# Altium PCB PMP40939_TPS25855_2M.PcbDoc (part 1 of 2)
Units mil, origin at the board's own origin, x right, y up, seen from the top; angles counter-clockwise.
Board outline 1968.5 x 1377.95 mil, 4 copper layers (Top Layer, Signal Layer 1, Signal Layer 2, Bottom Layer), stack 64.835 mil thick; 75 components, 24 nets, 187 pads, 267 vias.
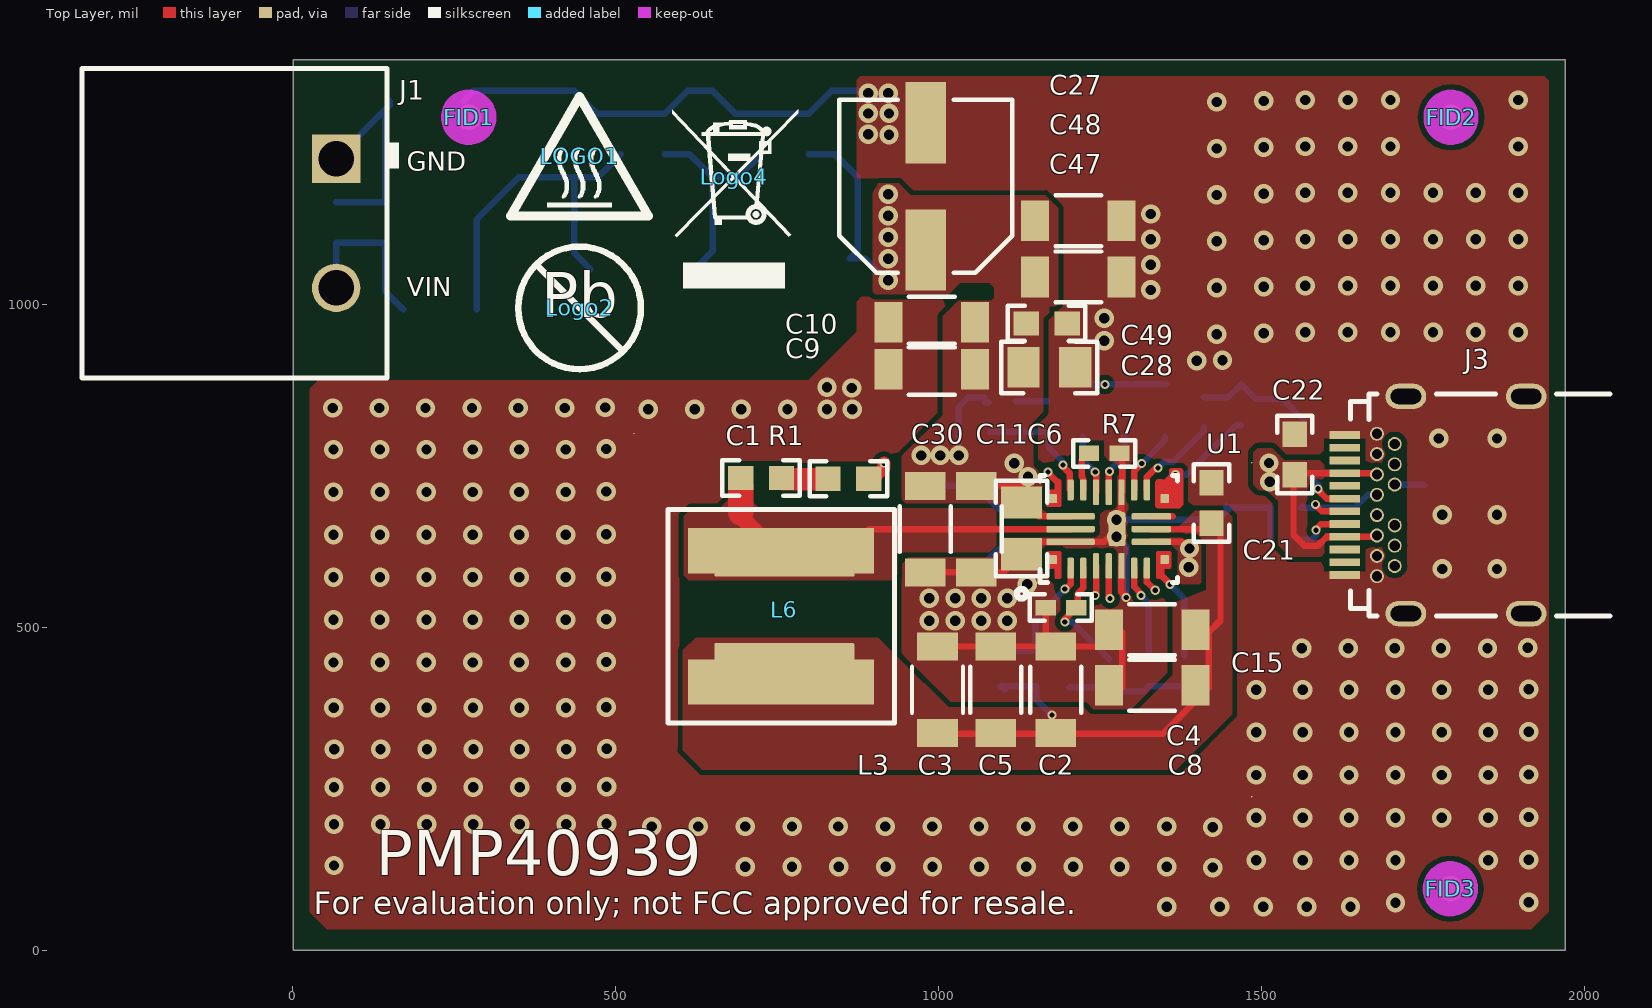
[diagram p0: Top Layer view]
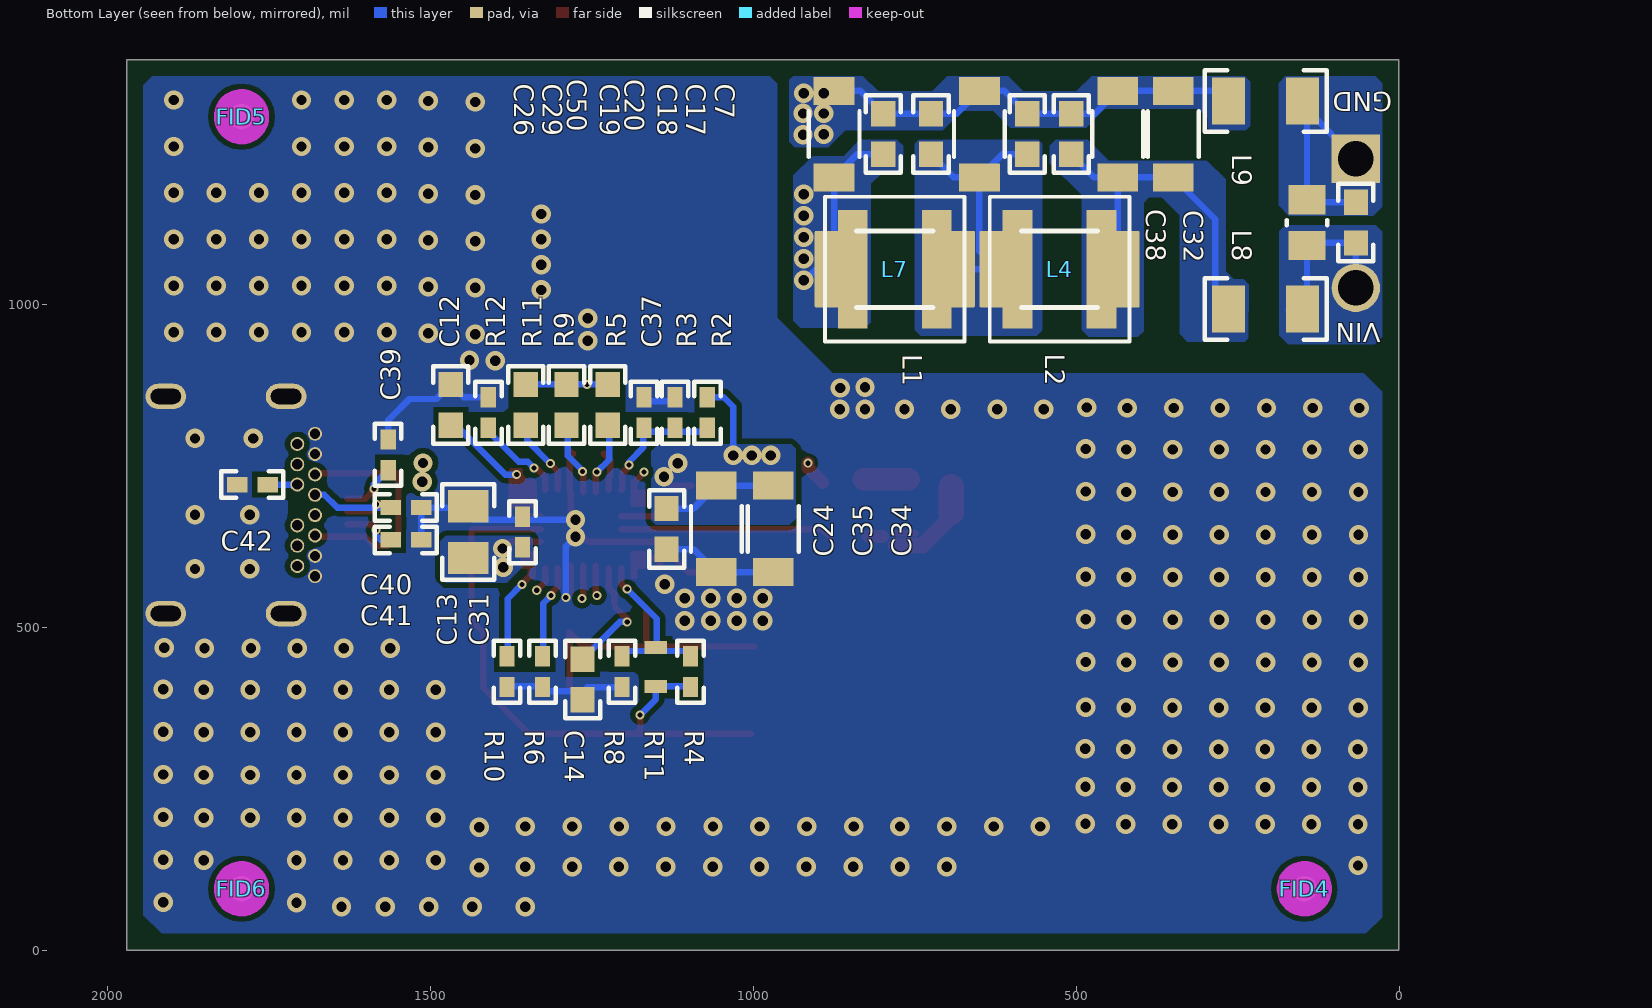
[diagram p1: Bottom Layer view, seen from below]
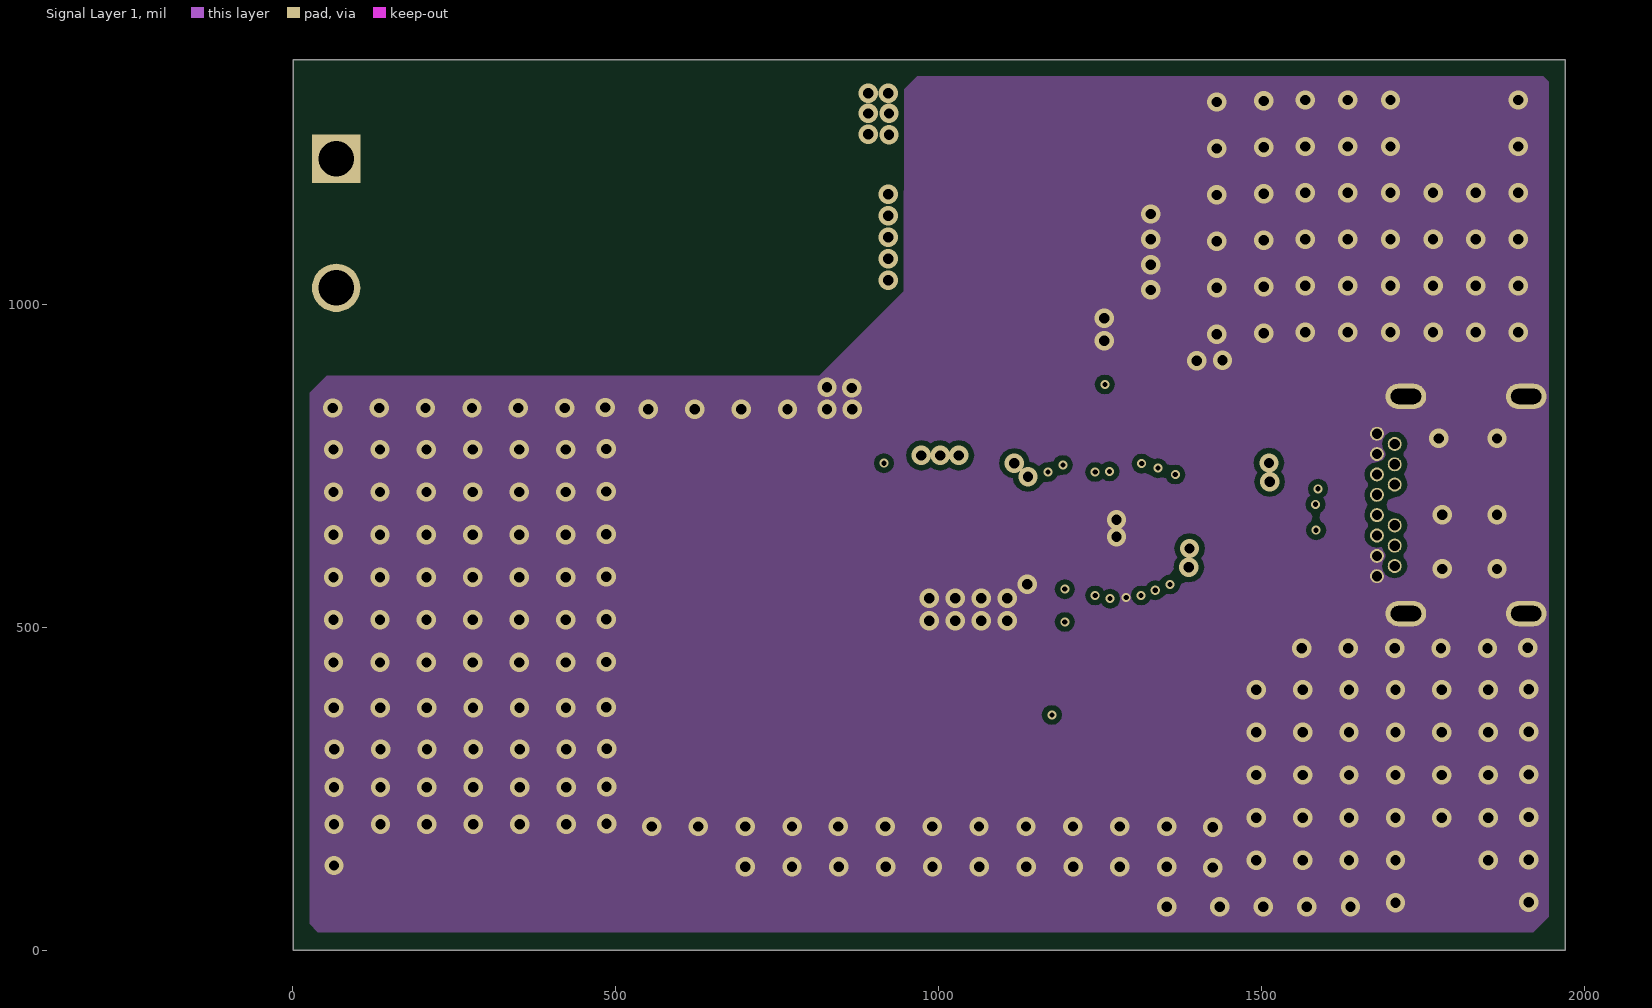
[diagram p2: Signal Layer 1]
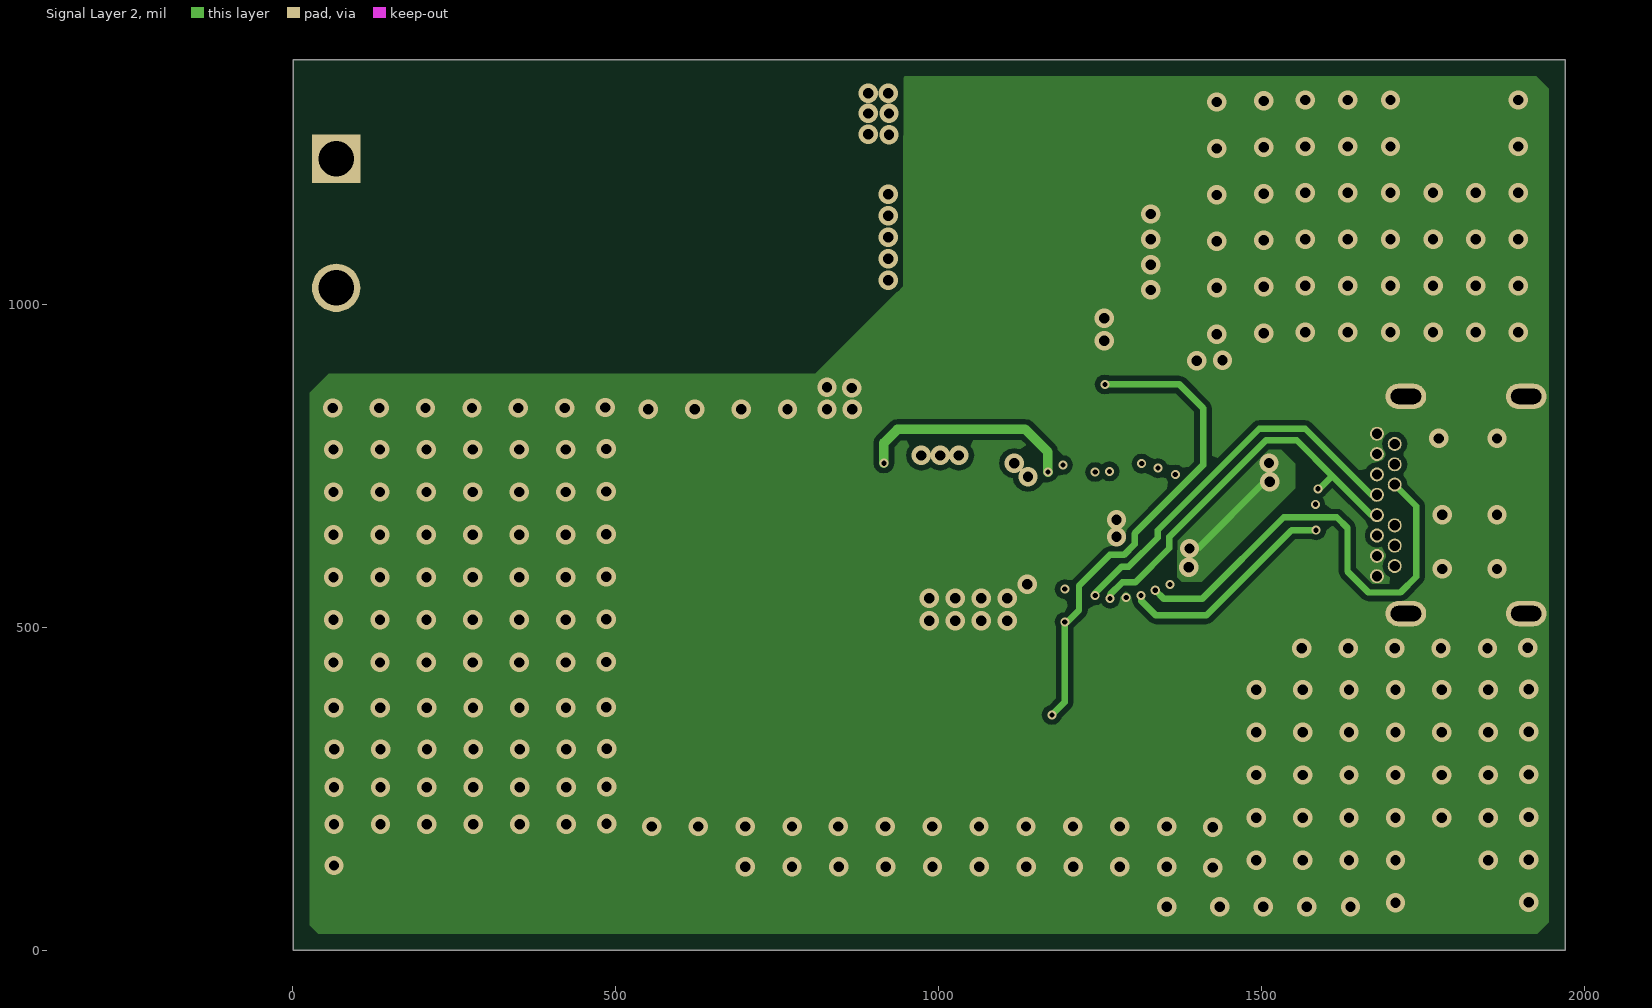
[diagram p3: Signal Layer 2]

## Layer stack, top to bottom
Top Solder: solder mask 0.4, Solder Resist, Dk 3.5
Top Layer: signal copper 1.4
Signal Layer 1: signal copper 1.4173
Signal Layer 2: signal copper 1.4173
Dielectric1: core 59.2, FR-4, Dk 4.8
Bottom Layer: signal copper 1.4
Bottom Solder: solder mask 0.4, Solder Resist, Dk 3.5

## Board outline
0.81,0.01 0.81,1377.96 1969.31,1377.96 1969.31,0.01

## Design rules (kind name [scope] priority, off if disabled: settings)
AcuteAngle [All] p1: minimum=4.50000000000000E+0001 checktracksonly=FALSE
AssemblyTestPointUsage [All] p1: valid=2
BoardOutlineClearance BoardOutlineClearance_MountingHoles [OnCopper and InComponentClass('Mounting Holes')] p1: gap=25 ignorepadtopadclearanceinfootprint=FALSE
BoardOutlineClearance BoardOutlineClearance_Poly [OnCopper and IsPoly] p2: gap=25 ignorepadtopadclearanceinfootprint=FALSE
BoardOutlineClearance [OnCopper and Not InComponentClass('Logo') and not InComponentClass('FiducialMark') and not InRegion(1000,500,4000,800) and not InPoly] p3: gap=24 ignorepadtopadclearanceinfootprint=FALSE
Clearance Clearance_1 [All] p1: gap=8 ignorepadtopadclearanceinfootprint=FALSE
Clearance Clearance_Keepouts [((IsTrack Or IsArc) And Not InPoly) And IsFree and IsKeepOut vs ((IsTrack Or IsArc) And Not InPoly) And IsFree and IsKeepOut] p2: gap=0 ignorepadtopadclearanceinfootprint=FALSE
Clearance Clearance_Poly [InPolygon] p3: gap=10 ignorepadtopadclearanceinfootprint=TRUE
Clearance Clearance_FiducialMark [IsKeepOut and InComponentClass('FiducialMark') vs IsPad and InComponentClass('FiducialMark')] p4: gap=0 ignorepadtopadclearanceinfootprint=FALSE
Clearance [All] p5: gap=6 ignorepadtopadclearanceinfootprint=TRUE
ComponentClearance ComponentClearance_MountingHoles_FiducialMarks [InComponentClass('Mounting Holes') vs InComponentClass('FiducialMark')] p1: gap=50 collisioncheckmode=3 verticalgap=10 showdistances=FALSE
ComponentClearance ComponentClearance_Shunt [InComponentClass('Header') vs InComponentClass('Shunt')] p2: gap=0 collisioncheckmode=3 verticalgap=0 showdistances=FALSE
ComponentClearance ComponentClearance_Logo [InComponentClass('Logo')] p3: gap=50 collisioncheckmode=3 verticalgap=10 showdistances=FALSE
ComponentClearance ComponentClearance_ScrewToNut [(HasFootprint('NY PMS 440 0025 PH')) vs (HasFootprint('Keystone_1902C'))] p4: gap=5 collisioncheckmode=3 verticalgap=10 showdistances=FALSE
ComponentClearance ComponentClearance_MountingHoles [InComponentClass('Mounting Holes')] p5: gap=250 collisioncheckmode=3 verticalgap=100000 showdistances=FALSE
ComponentClearance ComponentClearance_SmallPassives [HasFootprint('0201*') or HasFootprint('0402*') or HasFootprint('0508') or HasFootprint('0603*') or HasFootprint('0612') or HasFootprint('0805*') or HasFootprint('0815*') or HasFootprint('0830*') or HasFootprint('1206*') or HasFootprint('1210*') or HasFootprint('1808*') or HasFootprint('1812*') or HasFootprint('1825*') or HasFootprint('2010*') or HasFootprint('2220*') or HasFootprint('2225*') or HasFootprint('2512*') or HasFootprint('2728*') or HasFootprint('3518*') vs HasFootprint('0201*') or HasFootprint('0402*') or HasFootprint('0508') or HasFootprint('0603*') or HasFootprint('0612') or HasFootprint('0805*') or HasFootprint('0815*') or HasFootprint('0830*') or HasFootprint('1206*') or HasFootprint('1210*') or HasFootprint('1808*') or HasFootprint('1812*') or HasFootprint('1825*') or HasFootprint('2010*') or HasFootprint('2220*') or HasFootprint('2225*') or HasFootprint('2512*') or HasFootprint('2728*') or HasFootprint('3518*')] p6: gap=10 collisioncheckmode=3 verticalgap=10 showdistances=FALSE
ComponentClearance ComponentClearance_THtoSMT [IsThruComponent vs IsSMTComponent] p7: gap=40 collisioncheckmode=3 verticalgap=30 showdistances=FALSE
ComponentClearance ComponentClearance_THtoTH [IsThruComponent vs IsThruComponent] p8: gap=30 collisioncheckmode=3 verticalgap=30 showdistances=FALSE
ComponentClearance [All] p9: gap=30 collisioncheckmode=3 verticalgap=10 showdistances=FALSE
DiffPairsRouting [All] p1: maxlimit=100 minlimit=8 mostfreqgap=10 toplayer_minwidth=10 toplayer_maxwidth=15 toplayer_prefwidth=10 midlayer1_minwidth=10 midlayer1_maxwidth=15 midlayer1_prefwidth=10 midlayer2_minwidth=10 midlayer2_maxwidth=15 midlayer2_prefwidth=10 bottomlayer_minwidth=10 bottomlayer_maxwidth=15 bottomlayer_prefwidth=10 maxuncoupledlength=1000
FabricationTestPointUsage TestPointUsage [All] p1: valid=2 allowmultiple=FALSE
FabricationTestpoint Testpoint [All] p1: side=3 testpointundercomponent=TRUE minsize=40 maxsize=100 preferedsize=60 minholesize=0 maxholesize=40 preferedholesize=32 testpointgrid=1 allowsidetop=TRUE allowsidebottom=TRUE usegrid=TRUE gridtolerance=0.01
FanoutControl Fanout_LCC [IsLCC] p1: bgadir=Out bgaviamode=Centered fanoutstyle=Auto fanoutdirection=Alternating viagrid=1 // Fanout_LCC (Default Rule)
FanoutControl Fanout_BGA [IsBGA] p2: bgadir=Out bgaviamode=Centered fanoutstyle=Auto fanoutdirection=Alternating viagrid=1 // Fanout_BGA (Default Rule)
FanoutControl Fanout_Default [All] p4: bgadir=Out bgaviamode=Centered fanoutstyle=Auto fanoutdirection=Alternating viagrid=1 // Fanout_Default (Default Rule)
FanoutControl Fanout_Small [(CompPinCount < 5)] p5: bgadir=Out bgaviamode=Centered fanoutstyle=Auto fanoutdirection=OutThenIn viagrid=1 // Fanout_Small (Default Rule)
HoleSize [All] p1: absolutevalues=TRUE maxlimit=251 minlimit=7.87 maxpercent=80.000 minpercent=20.000
HoleToHoleClearance [All] p1: gap=8 allowstackedmicrovias=TRUE
MinimumAnnularRing MinimumAnnularRing_ThermalPadVias [IsVia and InAnyComponent] p1: minimumring=3
MinimumAnnularRing [All] p2: minimumring=2
MinimumSolderMaskSliver MinimumSolderMaskSliver_Logo [InComponentClass('Logo') vs InComponentClass('Logo')] p1: minsoldermaskwidth=0.4
MinimumSolderMaskSliver [All] p2: minsoldermaskwidth=3.94
PlaneClearance [All] p1: clearance=10
PlaneConnect [All] p1: planeconnectstyle=Relief reliefexpansion=10 reliefentries=4 reliefconductorwidth=10 reliefairgap=10
PolygonConnect [All] p1: connectstyle=Direct reliefconductorwidth=10 reliefentries=4 polygonreliefangle="90 Angle" airgapwidth=10
RoutingVias ThermalPadVias [IsVia and InAnyComponent] p1: holewidth=7.87 width=19.68 viastyle="Through Hole" minholewidth=7.87 minwidth=19.68 maxholewidth=12.99 maxwidth=23.62
RoutingVias [All] p2: holewidth=16 width=30 viastyle="Through Hole" minholewidth=8 minwidth=12 maxholewidth=20 maxwidth=30
SilkToBoardRegionClearance [Not ((IsComment or IsDesignator) And (Hide <> 'False')) and not InRegion(1000,500,4000,800)] p1:
SilkToSilkClearance SilkToSilkClearance_Pb-FreeLogo [(HasFootprint('Pb-Free_Overlay_Medium') OR HasFootprint('Pb-Free_Overlay_Small')) vs (HasFootprint('Pb-Free_Overlay_Medium') OR HasFootprint('Pb-Free_Overlay_Small'))] p1: silktosilkclearance=0
SilkToSilkClearance [All] p2: silktosilkclearance=3.94
SilkToSolderMaskClearance SilkToComponentPadClearance [(IsPad or IsFill or IsRegion) and InAnycomponent] p1: minsilkscreentomaskgap=5 clearancetoexposedcopper=TRUE
SilkToSolderMaskClearance "Silk to Solder Mask Opening" [All] p2: minsilkscreentomaskgap=3.94 clearancetoexposedcopper=FALSE
SolderMaskExpansion [All] p1: expansion=1.97
UnRoutedNet [All] p1: checkbadconnections=TRUE
Width [All] p1: maxlimit=100 minlimit=6 preferedwidth=10 checkconnectedcopper=TRUE
12 further rules are at their usual default settings.

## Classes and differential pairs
component class PMP40939_TPS25855_2M_1: C1 C2 C3 C4 C5 C6 C7 C8 C9 C10 C11 C12 C13 C14 C15 C17 C18 C19 C20 C21 C22 C24 C26 C27 C28 C29 C30 C31 C32 C34 C35 C37 C38 C39 C40 C41 C42 C47 C48 C49 C50 C? J1 J3 L1 L2 L3 L4 L6 L7 L8 L9 R1 R2 R3 R4 R5 R6 R7 R8 R9 R10 R11 R12 R? RT1 U1
component class PMP40939_TPS25855_2M_2: FID1 FID2 FID3 FID4 FID5 FID6 LOGO1 Logo2 Logo3 Logo4
component class FiducialMark: FID1 FID2 FID3 FID4 FID5 FID6

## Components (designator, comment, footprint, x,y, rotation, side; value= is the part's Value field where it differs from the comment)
C1 "C0603C104K5RACAUTO" 0603 725.01,730.69 r0 top value=0.1uF
C2 "GRM31CR71A226ME15L" 1206_180 1180.93,403 r90 top value=22uF
C3 "GRM31CR71A226ME15L" 1206_180 998,403 r90 top value=22uF
C4 "22 uF" 1206_180 1330,496 r180 top value=22uF
C5 "GRM31CR71A226ME15L" 1206_180 1088,403 r90 top value=22uF
C6 "CL21B104MBCNNNC" 0805_HV 1128.01,652.69 r270 top value=0.1uF
C7 "CGA5L1X7R1H106K160AC" 1206_190 349.81,1263.01 r90 bottom value=10uF
C8 "GRM31CR71A226ME15L" 1206_180 1330,410 r180 top value=22uF
C9 "GRT31CR61H106KE01L" 1206_180 989,899 r180 top value=10uF
C10 "GRT31CR61H106KE01L" 1206_180 989,972 r180 top value=10uF
C11 "GRT31CR61H106KE01L" 1206_180 1058.01,651.76 r270 top value=10uF
C12 "885012106018" 0603 1468,844 r90 bottom value=2.2uF
C13 "C2012X7R1A106M125AC" 0805_HV 1441,647 r90 bottom value=10uF
C14 "885012106018" 0603 1264,419 r270 bottom value=2.2uF
C15 "GRM155R71C104JA88D" 0402 1189,530 r180 top value=0.1uF
C17 "GCM31CR71H225KA55L" 1206_180 435.81,1263.01 r90 bottom value=2.2uF
C18 "C0603C222K5RACTU" 0603 507.81,1263.01 r90 bottom value=2200pF
C19 "GCM31CR71H225KA55L" 1206_180 649.81,1263.01 r90 bottom value=2.2uF
C20 "C0603C222K5RACTU" 0603 575.81,1263.01 r90 bottom value=2200pF
C21 "C0603C104K5RACAUTO" 0603 1422,692 r90 top value=0.1uF
C22 "C0603C104K5RACAUTO" 0603 1551,767 r90 top value=0.1uF
C24 "C0603C104K5RACAUTO" 0603 1134,652 r270 bottom value=0.1uF
C26 "GCM31CR71H225KA55L" 1206_180 874.81,1263.01 r90 bottom value=2.2uF
C27 "EEHZKV121XUP" SM_RADIAL_D8 980,1182 r90 top value=120uF
C28 "0.1 µF" 0805_HV 1171,902 r0 top value=0.1uF
C29 "C0603C222K5RACTU" 0603 798.81,1263.01 r90 bottom value=2200pF
C30 "GRT31CR61H106KE01L" 1206_180 979.01,651.69 r270 top value=10uF
C31 "GRM155R71C104JA88D" 0402 1357,647 r90 bottom value=0.1uF
C32 "0.1 µF" 0603 67.17,1126.01 r90 bottom value=0.1uF
C34 "10 uF" 1206_180 969,652 r270 bottom value=10uF
C35 "GRT31CR61H106KE01L" 1206_180 1057,652 r270 bottom value=10uF
C37 "C0402C104K4RACAUTO" 0402 1169,832.02 r90 bottom value=0.1uF
C38 "CEU4J2X7R1H104K125AE" 0805_150 142.81,1126.01 r90 bottom value=0.1uF
C39 "GRM155R71C104JA88D" 0402 1565,766.62 r90 bottom value=0.1uF
C40 "GRM155R71C104JA88D" 0402 1537.5,685 r180 bottom value=0.1uF
C41 "GRM155R71C104JA88D" 0402 1537.5,635 r180 bottom value=0.1uF
C42 "GRM155R71C104JA88D" 0402 1775,720.47 r0 bottom value=0.1uF
C47 "10 uF" 1206_180 1216.01,1042 r0 top value=10uF
C48 "10 uF" 1206_180 1216.01,1129 r0 top value=10uF
C49 "GCM188R71H472KA37D" 0603 1167,970 r0 top value=4700pF
C50 "C0603C222K5RACTU" 0603 724.81,1263.01 r90 bottom value=2200pF
FID1 "Fiducial" Fiducial10-20 272.44,1289.01 r0 top
FID2 "Fiducial" Fiducial10-20 1792.81,1289.01 r0 top
FID3 "Fiducial" Fiducial10-20 1791.81,95.01 r0 top
FID4 "Fiducial" Fiducial10-20 147,95 r180 bottom
FID5 "Fiducial" Fiducial10-20 1792,1290 r180 bottom
FID6 "Fiducial" Fiducial10-20 1792,95 r180 bottom
J1 "1757242" PHOENIX_1757242 -90.19,1125.01 r270 top locked
J3 "632723300011" Wurth_632_723_300_011 2045,688.98 r90 top locked
L1 "74279252" 1812_170_HighSpeed 780.81,1054.01 r0 bottom value="880 ohm"
L2 "XAL5030-601MEB" XAL5030 525.81,1054.01 r0 bottom value=600nH
L3 "XAL8080-102ME" XAL8080 756.01,516.69 r270 top value=4.7uH
L4 "74279252" 1812_170_HighSpeed 525.81,1054.01 r0 bottom value="880 ohm"
L6 "XAL6060-102MEB" XAL6060 761.01,526.69 r270 top value=4.7uH
L7 "XAL5030-601MEB" XAL5030 780.81,1054.01 r0 bottom value=600nH
L8 "MPZ2012S300ATD25" 1206 206.92,992.01 r0 bottom value="30 ohm"
L9 "MPZ2012S300ATD25" 1206 206.92,1314.01 r0 bottom value="30 ohm"
LOGO1 "CAUTION HOT SURFACE" IEC_HotSurface_Small 444,1229 r0 top
Logo2 "Pb-Free Symbol" Pb-Free_Overlay_Medium 444,994 r0 top
Logo3 "FCC disclaimer" FCC_disclaimer -447.47,-218.99 r0 top
Logo4 "WEEE logo" WEEE_Minimum 683,1197 r0 top
R1 "CRCW060310R0JNEA" 0603 860.01,729.69 r180 top value=10
R2 "CRCW040220K0JNED" 0402 1071,832.02 r90 bottom value=20k
R3 "CRCW04025K10JNED" 0402 1121,832.02 r270 bottom value=5.1k
R4 "ERJ-2GEJ393X" 0402 1097,430.98 r270 bottom value=39k
R5 "CRCW0603100KFKEA" 0603 1225,844 r270 bottom value=100k
R6 "CRCW04025K10JNED" 0402 1326,430.98 r90 bottom value=5.1k
R7 "CRCW04028K87FKED" 0402 1256,769 r180 top value=8.87k
R8 "ERJ-2GEJ393X" 0402 1203,430.98 r90 bottom value=39k
R9 "CRCW0603100KFKEA" 0603 1289,844 r270 bottom value=100k
R10 "MCR01MZPJ000" 0402 1381,430.98 r90 bottom value=0
R11 "CRCW0603100KFKEA" 0603 1352,844 r270 bottom value=100k
R12 "CRCW04025K10JNED" 0402 1410,832.02 r270 bottom value=5.1k
RT1 "NCP18WM474J03RB" 0603S 1151,438.19 r270 bottom value=470k
U1 "Used in BOM report" RPQ0025A 1263.01,651.69 r90 top locked

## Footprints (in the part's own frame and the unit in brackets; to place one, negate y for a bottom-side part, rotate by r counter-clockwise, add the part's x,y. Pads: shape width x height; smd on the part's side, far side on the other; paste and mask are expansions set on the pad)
0402 [mm] "0402 from SM-752 data"
  rect 0.8x0.6 smd: 1(-0.6,0) 2(0.6,0)
  silkscreen extent -1.22,-0.52 1.22,0.52, body extent -0.55,-0.3 0.55,0.3, height 0.6
0603 [mm] "0603 from SM-752 data"
  rect 1x0.95 smd: 1(-0.8,0) 2(0.8,0)
  silkscreen extent -1.52,-0.69 1.52,0.69, body extent -0.87,-0.47 0.87,0.47, height 1
0603S [mil]
  rect 20x35 smd: 1(-30,0) 2(30,0)
  body extent -34,-19 34,19, height 39
0805_150 [mm] "0805 / 1.5 mm height"
  rect 1.15x1.45 smd: 1(-0.9,0) 2(0.9,0)
  silkscreen extent -0.1,-0.8 0.1,0.8, body extent -1.1,-0.72 1.1,0.72, height 1.5
0805_HV [mil] "0805 with 30mil clearance between pads"
  rect 50x63 smd: 1(-40,0) 2(40,0)
  silkscreen extent -74,-40 74,40, body extent -43,-29 43,29, height 57
1206 [mm] "1206 from SM-752 data"
  rect 1.3x1.85 smd: 1(-1.45,0) 2(1.45,0)
  silkscreen extent -2.4,-1.21 2.4,1.21, body extent -1.7,-0.9 1.7,0.9, height 1.35
1206_180 [mm] "1206_180"
  rect 1.1x1.6 smd: 1(-1.7,0) 2(1.7,0)
  silkscreen extent -0.9,-1 0.9,1, body extent -1.75,-0.95 1.75,0.95, height 1.8
1206_190 [mm] "1206_190"
  rect 1.1x1.6 smd: 1(-1.7,0) 2(1.7,0)
  silkscreen extent -0.9,-1 0.9,1, body extent -1.75,-0.95 1.75,0.95, height 1.9
1812_170_HighSpeed [mm] "Wurth recommended land pattern"
  rrect7% 1.4x3 smd: 1(-2.45,0) 2(2.45,0)
  silkscreen extent -1.5,-1.5 1.5,1.5, body extent -2.25,-1.6 2.25,1.6, height 1.51
FCC_disclaimer [mil]
Fiducial10-20 [mm]
  round 1 smd mask+0.5: 1(0,0)
  Top Layer keep-out circle w1.178: c0,0 r0.5
IEC_HotSurface_Small [mil]
  silkscreen extent -107,-93 107,92
Pb-Free_Overlay_Medium [mil]
  silkscreen extent -95,-95 95,95
PHOENIX_1757242 [mm] "Header, 5.08 mm, 2x1, R/A, TH"
  rect 1.9x1.9 hole 1.4: 1(-2.54,4)
  round 1.9 hole 1.4: 2(2.54,4)
  silkscreen extent -6.08,-6 6.08,6.47, body extent -6.06,-6.02 6.1,5.98, height 8.6
RPQ0025A [mm] "VQFN-25"
  rrect29% 0.35x0.35 smd: 1(-1.2,2.2) 9(-1.2,-2.2) 13(1.2,-2.2) 21(1.2,2.2)
  rrect40% 0.825x0.25 smd: 2(-1.538,1.5) 3(-1.538,1) 7(-1.538,-1) 8(-1.538,-1.5) 14(1.538,-1.5) 15(1.538,-1) 19(1.538,1) 20(1.538,1.5)
  rrect40% 1x0.25 smd: 4(-1.45,0.5) 5(-1.45,0) 6(-1.45,-0.5) 16(1.45,-0.5) 17(1.45,0) 18(1.45,0.5)
  rrect40% 0.25x1.55 smd paste-1.55: 10(-0.5,-1.675) 11(0,-1.675) 12(0.5,-1.675)
  rrect40% 0.25x1.9 smd paste-1.55: 22(0.5,1.5) 23(0,1.5) 24(-0.5,1.5)
  rrect15% 1.325x0.65 smd paste-1.325: 25(0,-0.325)
  Top Layer region: -1.95,1.925 -1.95,2.075 -1.946,2.094 -1.935,2.11 -1.919,2.121 -1.9,2.125 -1.9,2.125 -1.6,2.125 -1.581,2.129 -1.565,2.14 -1.554,2.156 -1.55,2.175 -1.55,2.175 -1.55,2.4 -1.546,2.419 -1.535,2.435 -1.519,2.446 -1.5,2.45 -1.5,2.45 -0.925,2.45 -0.906,2.446 -0.89,2.435 -0.879,2.419 -0.875,2.4 -0.875,2.4 -0.875,1.925 -0.879,1.906 -0.89,1.89 -0.906,1.879 -0.925,1.875 -0.925,1.875 -1.9,1.875 -1.919,1.879 -1.935,1.89 -1.946,1.906 -1.95,1.925
  Top Layer region: -1.95,-1.925 -1.95,-2.075 -1.946,-2.094 -1.935,-2.11 -1.919,-2.121 -1.9,-2.125 -1.9,-2.125 -1.6,-2.125 -1.581,-2.129 -1.565,-2.14 -1.554,-2.156 -1.55,-2.175 -1.55,-2.175 -1.55,-2.4 -1.546,-2.419 -1.535,-2.435 -1.519,-2.446 -1.5,-2.45 -1.5,-2.45 -0.925,-2.45 -0.906,-2.446 -0.89,-2.435 -0.879,-2.419 -0.875,-2.4 -0.875,-2.4 -0.875,-1.925 -0.879,-1.906 -0.89,-1.89 -0.906,-1.879 -0.925,-1.875 -0.925,-1.875 -1.9,-1.875 -1.919,-1.879 -1.935,-1.89 -1.946,-1.906 -1.95,-1.925
  Top Layer region: 1.95,-1.925 1.95,-2.075 1.946,-2.094 1.935,-2.11 1.919,-2.121 1.9,-2.125 1.9,-2.125 1.6,-2.125 1.575,-2.132 1.557,-2.15 1.55,-2.175 1.55,-2.175 1.55,-2.4 1.546,-2.419 1.535,-2.435 1.519,-2.446 1.5,-2.45 1.5,-2.45 0.925,-2.45 0.906,-2.446 0.89,-2.435 0.879,-2.419 0.875,-2.4 0.875,-2.4 0.875,-1.925 0.882,-1.9 0.9,-1.882 0.925,-1.875 0.925,-1.875 1.9,-1.875 1.919,-1.879 1.935,-1.89 1.946,-1.906 1.95,-1.925
  Top Layer region: 1.95,1.925 1.95,2.075 1.946,2.094 1.935,2.11 1.919,2.121 1.9,2.125 1.9,2.125 1.6,2.125 1.575,2.132 1.557,2.15 1.55,2.175 1.55,2.175 1.55,2.4 1.546,2.419 1.535,2.435 1.519,2.446 1.5,2.45 1.5,2.45 0.925,2.45 0.906,2.446 0.89,2.435 0.879,2.419 0.875,2.4 0.875,2.4 0.875,1.925 0.882,1.9 0.9,1.882 0.925,1.875 0.925,1.875 1.9,1.875 1.919,1.879 1.935,1.89 1.946,1.906 1.95,1.925
  silkscreen extent -2.1,-2.7 2.1,2.7, body extent -1.75,-2.25 1.75,2.25, height 1
SM_RADIAL_D8 [mm] "6.3 x 7.7mm:  Panasonic D8"
  rect 3.2x1.6 smd: 1(-2.5,0) 2(2.5,0)
  silkscreen extent -3.4,-3.4 3.4,3.4, body extent -3.4,-3.4 3.4,3.4, height 8.01
WEEE_Minimum [mil] "WEEElie bin"
  silkscreen extent -95,-172 99,104
Wurth_632_723_300_011 [mm] "Connector, Receptacle, USB Type C, R/A"
  rect 0.3x1.2 smd: A1(-2.75,10.58) A2(-2.25,10.58) A3(-1.75,10.58) A4(-1.25,10.58) A5(-0.75,10.58) A6(-0.25,10.58) A7(0.25,10.58) A8(0.75,10.58) A9(1.25,10.58) A10(1.75,10.58) A11(2.25,10.58) A12(2.75,10.58)
  round 0.55 hole 0.4: B1(2.8,9.32) B2(2.4,8.62) B3(1.6,8.62) B4(1.2,9.32) B5(0.8,8.62) B6(0.4,9.32) B7(-0.4,9.32) B8(-0.8,8.62) B9(-1.2,9.32) B10(-1.6,8.62) B11(-2.4,8.62) B12(-2.8,9.32) M1(2,9.32) M2(-2,9.32)
  rrect100% 1x1.6 hole 0.6 slot 1.2 at 90 deg: S1(-4.27,8.18) S2(-4.27,3.45) S3(4.27,3.45) S4(4.27,8.18)
  silkscreen extent -4.37,0.15 4.37,10.36, body extent -4.37,-0.96 4.37,10.83, height 3.07
XAL5030 [mil] "Coilcraft XAL5030 12/12/11"
  rect 46x183 smd: 1(-65,0) 2(65,0)
  silkscreen extent -108,-112 108,112, body extent -108,-112 108,112, height 122
XAL6060 [mm] "Coilcraft recommended land pattern Document 887-4 Revised 01/14/18"
  rrect7% 1.43x5.5 smd: 1(-2.019,0) 2(2.019,0)
  body extent -3.28,-3.38 3.28,3.38, height 6.11
XAL8080 [mm] "Coilcraft"
  rect 1.78x7.31 smd: 1(-2.58,0) 2(2.58,0)
  silkscreen extent -4.2,-4.45 4.2,4.45, body extent -4.15,-4.4 4.15,4.4, height 8

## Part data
C1 C21 C22 C24: library part CMP-0079602-1, "CAP, CERM, 0.1 µF, 50 V,+/- 10%, X7R, AEC-Q200 Grade 1, 0603", Cap_Case=0603, Manufacturer=Kemet, Supplier Part Number 1=399-6856-1-ND, TempCo=X7R, Tolerance_%=10%, Value2=50V, ValueDisplayed=0.1µF
C2 C3 C5 C8: library part CMP-0008960-2, "CAP, CERM, 22 uF, 10 V, +/- 20%, X7R, 1206", Cap_Case=1206, Manufacturer=MuRata, Supplier Part Number 1=490-6516-1-ND, TempCo=X7R, Tolerance_%=20%, Value1=Unknown, Value2=10V, ValueDisplayed=22uF
C4: library part CMP-0008960-2, "CAP, CERM, 22 uF, 10 V, +/- 20%, X7R, 1206", Cap_Case=1206, Manufacturer=MuRata, PartNumber=GRM31CR71A226ME15L, Supplier Part Number 1=490-6516-1-ND, TempCo=X7R, Tolerance_%=20%, Value1=Unknown, Value2=10V
C6: library part CMP-0082524-1, "CAP, CERM, 0.1 µF, 50 V,+/- 20%, X7R, 0805", Cap_Case=0805, Manufacturer=Samsung, Supplier Part Number 1=1276-2450-1-ND, TempCo=X7R, Tolerance_%=20%, Value2=50V, ValueDisplayed=0.1µF
C7: library part CMP-0085950-1, "CAP, CERM, 10 µF, 50 V,+/- 10%, X7R, AEC-Q200 Grade 1, 1206", Cap_Case=1206, Manufacturer=TDK, TempCo=X7R, Tolerance_%=10%, Value2=50V, ValueDisplayed=10µF
C9 C10 C11 C30 C35: library part CMP-0009015-1, "CAP, CERM, 10 uF, 50 V, +/- 10%, X5R, AEC-Q200 Grade 1, 1206", Cap_Case=1206, Manufacturer=MuRata, Supplier Part Number 1=490-12456-1-ND, TempCo=X5R, Tolerance_%=10%, Value1=Unknown, Value2=50V, ValueDisplayed=10uF
C12 C14: library part CMP-0006825-5, "CAP, CERM, 2.2 uF, 16 V, +/- 20%, X5R, 0603", Cap_Case=0603, Manufacturer="Wurth Elektronik", Supplier Part Number 1=732-7915-1-ND, TempCo=X5R, Tolerance_%=20%, Value1=Unknown, Value2=16V, ValueDisplayed=2.2uF
C13: library part CMP-0007864-2, "CAP, CERM, 10 uF, 10 V, +/- 20%, X7R, 0805", Cap_Case=0805, Manufacturer=TDK, Supplier Part Number 1=445-7592-1-ND, TempCo=X7R, Tolerance_%=20%, Value1=Unknown, Value2=10V, ValueDisplayed=10uF
C15 C31 C39 C40 C41 C42: library part CMP-0006640-2, "CAP, CERM, 0.1 uF, 16 V, +/- 5%, X7R, 0402", Cap_Case=0402, Manufacturer=MuRata, Supplier Part Number 1=490-6327-1-ND, TempCo=X7R, Tolerance_%=5%, Value1=Unknown, Value2=16V, ValueDisplayed=0.1uF
C17 C19 C26: library part CMP-0008814-2, "CAP, CERM, 2.2 uF, 50 V, +/- 10%, X7R, AEC-Q200 Grade 1, 1206", Cap_Case=1206, Manufacturer=MuRata, Supplier Part Number 1=490-4796-1-ND, TempCo=X7R, Tolerance_%=10%, Value1=Unknown, Value2=50V, ValueDisplayed=2.2uF
C18 C20 C29 C50: library part CMP-0006898-4, "CAP, CERM, 2200 pF, 50 V, +/- 10%, X7R, 0603", Cap_Case=0603, Manufacturer=Kemet, Supplier Part Number 1=399-1085-1-ND, TempCo=X7R, Tolerance_%=10%, Value1=Unknown, Value2=50V, ValueDisplayed=2200pF
C27: library part CMP-0010724-1, "CAP, AL, 120 uF, 35 V, +/- 20%, 0.035 ohm, AEC-Q200 , SMD", Cap_Case=D8, Manufacturer=Panasonic, Tolerance_%=20%, Value1="0.035 ohm", Value2=35V, ValueDisplayed=120uF
C28: library part CMP-0082524-1, "CAP, CERM, 0.1 µF, 50 V,+/- 20%, X7R, 0805", Cap_Case=0805, Manufacturer=Samsung, PartNumber=CL21B104MBCNNNC, Supplier Part Number 1=1276-2450-1-ND, TempCo=X7R, Tolerance_%=20%, Value2=50V, ValueDisplayed=0.1µF
C32: library part CMP-0079602-1, "CAP, CERM, 0.1 µF, 50 V,+/- 10%, X7R, AEC-Q200 Grade 1, 0603", Cap_Case=0603, Manufacturer=Kemet, PartNumber=C0603C104K5RACAUTO, Supplier Part Number 1=399-6856-1-ND, TempCo=X7R, Tolerance_%=10%, Value2=50V
C34 C47 C48: library part CMP-0009015-1, "CAP, CERM, 10 uF, 50 V, +/- 10%, X5R, AEC-Q200 Grade 1, 1206", Cap_Case=1206, Manufacturer=MuRata, PartNumber=GRT31CR61H106KE01L, Supplier Part Number 1=490-12456-1-ND, TempCo=X5R, Tolerance_%=10%, Value1=Unknown, Value2=50V
C37: library part CMP-0006237-2, "CAP, CERM, 0.1 uF, 16 V, +/- 10%, X7R, AEC-Q200 Grade 1, 0402", Cap_Case=0402, Manufacturer=Kemet, Supplier Part Number 1=399-6828-1-ND, TempCo=X7R, Tolerance_%=10%, Value1=Unknown, Value2=16V, ValueDisplayed=0.1uF
C38: library part CMP-0007961-2, "CAP, CERM, 0.1 uF, 50 V, +/- 10%, X7R, AEC-Q200 Grade 1, 0805", Cap_Case=0805, Manufacturer=TDK, Supplier Part Number 1=445-7856-1-ND, TempCo=X7R, Tolerance_%=10%, Value1=Unknown, Value2=50V, ValueDisplayed=0.1uF
C49: library part CMP-0007146-4, "CAP, CERM, 4700 pF, 50 V, +/- 10%, X7R, AEC-Q200 Grade 1, 0603", Cap_Case=0603, Manufacturer=MuRata, Supplier Part Number 1=490-4932-1-ND, TempCo=X7R, Tolerance_%=10%, Value1=Unknown, Value2=50V, ValueDisplayed=4700pF
FID1 FID2 FID3 FID4 FID5 FID6: library part CMP-0077181-1, "Fiducial mark.  There is nothing to buy or mount.", Manufacturer=N/A
J1: library part CMP-0055534-1, "Header (Shrouded), 5.08 mm, 2x1, Tin, R/A, TH", Manufacturer="Phoenix Contact", Supplier Part Number 1=277-1106-ND
J3: library part CMP-0080891-1, "Connector, Receptacle, USB Type C, R/A", Color=Black, Current_A=3A, Manufacturer="Wurth Elektronik", Supplier Part Number 1=732-9618-1-ND, Voltage_V=5V
L1 L4: library part CMP-0003170-1, "Ferrite Bead, 880 ohm @ 100 MHz, 4 A, 1812", Manufacturer="Wurth Elektronik", Value1="0.035 ohm", Value2=4A, ValueDisplayed="880 ohm"
L2 L7: library part CMP-0061005-2, "Inductor, Shielded, Composite, 600 nH, 17.7 A, 0.00411 ohm, AEC-Q200 Grade 1, SMD", Manufacturer=Coilcraft, Value1="0.00411 ohm", Value2=17.7A, ValueDisplayed=600nH
L3: library part CMP-0061062-1, "Inductor, Shielded, Composite, 4.7 uH, 10.5 A, 0.00889 ohm, SMD", Manufacturer=Coilcraft, PartNumber=XAL8080-472ME, Supplier Part Number 1=994-XAL8080-472MEB, Value1="0.00889 ohm", Value2=10.5A
L6: library part CMP-0061020-2, "Inductor, Shielded, Composite, 4.7 µH, 10.5 A, 0.0144 ohm, AEC-Q200 Grade 1, SMD", Manufacturer=Coilcraft, PartNumber=XAL6060-472MEB, Value1="0.0144 ohm", Value2=10.5A, ValueDisplayed=1uH
L8 L9: library part CMP-0003139-1, "Ferrite Bead, 30ohm @ 100 MHz, 6 A, 0805", Manufacturer=TDK, Value1="0.010 ohm", Value2=6A, ValueDisplayed=30ohm
LOGO1: library part CMP-0074837-1, "IEC 61010-1 Hot Surface Warning"
Logo2: library part CMP-0074839-1
Logo3: library part CMP-0074847-1, "FCC_disclaimer"
Logo4: library part CMP-0074769-1
R1: library part CMP-0025703-4, "RES, 10, 5%, 0.1 W, AEC-Q200 Grade 0, 0603", Manufacturer=Vishay-Dale, Power_W=100mW, Supplier Part Number 1=541-10GCT-ND, TempCo="200 ppm/C", Tolerance_%=5%, Value2=0.1W, Value_Code=10R0, ValueDisplayed=10
R2: library part CMP-0026875-3, "RES, 20 k, 5%, 0.063 W, AEC-Q200 Grade 0, 0402", Manufacturer=Vishay-Dale, Power_W=63mW, Supplier Part Number 1=541-20KJCT-ND, TempCo="200 ppm/C", Tolerance_%=5%, Value2=0.063W, Value_Code=20k0, ValueDisplayed=20k
R3 R6 R12: library part CMP-0026951-5, "RES, 5.1 k, 5%, 0.063 W, AEC-Q200 Grade 0, 0402", Manufacturer=Vishay-Dale, Power_W=63mW, Supplier Part Number 1=541-5.1KJCT-ND, TempCo="200 ppm/C", Tolerance_%=5%, Value2=0.063W, Value_Code=5k10, ValueDisplayed=5.1k
R4 R8: library part CMP-0026998-2, "RES, 39 k, 5%, 0.1 W, AEC-Q200 Grade 0, 0402", Manufacturer=Panasonic, Power_W=100mW, Supplier Part Number 1=P39KJCT-ND, TempCo="200 ppm/C", Tolerance_%=5%, Value2=0.1W, Value_Code=39k0, ValueDisplayed=39k
R5 R9 R11: library part CMP-0021990-1, "RES, 100 k, 1%, 0.1 W, 0603", Manufacturer=Vishay-Dale, Power_W=100mW, Supplier Part Number 1=541-100KHCT-ND, TempCo="100 ppm/C", Tolerance_%=1%, Value2=0.1W, Value_Code=100k
R7: library part CMP-0026592-2, "RES, 8.87 k, 1%, 0.063 W, AEC-Q200 Grade 0, 0402", Manufacturer=Vishay-Dale, Power_W=63mW, Supplier Part Number 1=541-8.87KLCT-ND, TempCo="100 ppm/C", Tolerance_%=1%, Value2=0.063W, Value_Code=8k87, ValueDisplayed=8.87k
R10: library part CMP-0027002-2, "RES, 0, 5%, 0.063 W, 0402", Manufacturer=Rohm, Power_W=63mW, Supplier Part Number 1=RHM0.0JCT-ND, TempCo="500 ppm/C", Tolerance_%=5%, Value2=0.063W, Value_Code=0000, ValueDisplayed=0
RT1: library part CMP-0002545-3, "Thermistor NTC, 470k ohm, 5%, 0603", Manufacturer=MuRata, Power_W=100mW, Supplier Part Number 1=490-2433-1-ND, Tolerance_%=5%
U1: library part Component_1, Alternate Manufacturer=-

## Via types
v1: diameter 30, hole 16, Top Layer to Bottom Layer, 246 vias
v2: diameter 14, hole 8, Top Layer to Bottom Layer, 21 vias

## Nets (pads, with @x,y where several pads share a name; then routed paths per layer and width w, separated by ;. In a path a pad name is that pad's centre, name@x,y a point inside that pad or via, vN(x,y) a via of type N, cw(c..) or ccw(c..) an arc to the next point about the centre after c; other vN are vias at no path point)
+BAT: C32.1 C38.1 J1.2 L8.1 | length 256.9
  Bottom Layer w10: J1.2@67.29,1025.01 67.29,1094.4 C32.1@67.17,1094.51 138.87,1094.51 C38.1@142.81,1090.57 142.81,1019.92 L8.1@170.72,992.01
-BAT: C32.2 C38.2 J1.1 L9.1 | length 339.5
  Bottom Layer w10: C32.2@67.17,1157.5 138.87,1157.5 C38.2@142.81,1161.44 L9.1@142.81,1300.53 ; J1.1@67.29,1225.01 L9.1@142.81,1300.53 ; L9.1@149.84,1314.01 149.84,1307.55 L9.1@142.81,1300.53
BOOT: R1.1 U1.21 | length 417.9
  Top Layer w10: R1.1@891.51,724.69 R1.1@892.37,723.83 ; v2@1170.01,738.69 1170.01,737.69 1184.01,723.69 1184.01,706.55
  Top Layer w20: R1.1@892.37,723.83 915,746.46 v2(915,753.69)
  Signal Layer 2 w15: v2(915,753.69) 915,785 936,806 1134,806 1168.51,771.49 1168.51,740.49 v2(1169,740)
EN: C37.1 R2.1 R3.2 U1.20 | length 194
  Top Layer w10: v2@1190.01,750.69 1203,737.71 1203,713.18 U1.20@1203.96,712.22
  Bottom Layer w10: R2.1@1079,802.38 1167,802.38 1170,799.38 1170,778 1192,756 v2(1192,751)
NetC1_2: C1.2 R1.2 | length 69
  Top Layer w35: C1.2@759.51,728.69 R1.2@828.52,728.69
NetC7_1: C7.1 C17.1 C18.1 L2.1 L4.1 L8.2 | length 556.1
  Bottom Layer w10: L8.2@284.9,992.01 284.9,1131.17 C7.1@349.81,1196.08 C17.1@435.81,1196.08 ; L2.1@460.81,1054.01 435.81,1079.01 C17.1@435.81,1196.08 ; C18.1@507.81,1231.51 472.38,1196.08 C17.1@435.81,1196.08
NetC19_1: C19.1 C20.1 C50.1 L1.1 L2.2 L4.2 L7.1 | length 425.4
  Bottom Layer w10: C20.1@575.81,1231.51 614.38,1231.51 C19.1@649.81,1196.08 ; L7.1@715.81,1054.01 L1.1@684.35,1054.01 L4.2@622.27,1054.01 649.81,1081.55 C19.1@649.81,1196.08 ; C50.1@724.81,1231.51 689.38,1196.08 C19.1@649.81,1196.08
NetR5_2: R5.2 U1.18 | length 94.1
  Top Layer w10: v2(1242,740) 1243.33,738.67 U1.18@1243.33,708.78
  Bottom Layer w10: R5.2@1223,794.5 1223,759 v2(1242,740)
NetR7_2: R7.2 U1.19 | length 62.2
  Top Layer w10: R7.2@1223.39,768.69 R7.2@1223.64,768.44 ; U1.19@1223.64,712.22 1223.64,729.07 1221.88,730.83 1221.88,732.7 1221,733.58 1221,758.3 R7.2@1231.39,768.69
NetR9_2: R9.2 U1.17 | length 100.5
  Top Layer w10: U1.17@1263.01,708.78 1263.01,742.62 v2@1264,741.64 ; v2@1263,742.68 v2@1264,741.68 ; v2(1264,741) v2@1264,741.64
  Bottom Layer w10: v2(1264,741) 1264,742 1287,765 R9.2@1287,794.5
NetR10_2: R10.2 U1.9 | length 142.7
  Top Layer w10: 1344.01,589.79 1344.01,580.69 v2@1354.01,570.69
  Bottom Layer w10: v2(1358,566) 1380,544 R10.2@1380,455.62
NetR11_2: R11.2 U1.15 | length 97.5
  Top Layer w10: U1.15@1302.38,712.22 1302.38,741.06 v2@1311.01,749.69
  Bottom Layer w10: v2(1314,753) 1350,789 R11.2@1350,794.5
NetR12_2: R12.2 U1.14 | length 139.7
  Top Layer w10: U1.14@1322.07,712.22 1322.07,732.46 1335.3,745.69 v2@1336.01,745.69
  Bottom Layer w10: v2(1339,746) 1349,756 1363,756 1410,803 R12.2@1410,808.4
OUT: C12.1 U1.13 | length 185.9
  Top Layer w10: U1.13@1349.63,698.94 1341,707.56 1341,713.13 1363.87,736 v2(1366,736)
  Bottom Layer w10: v2(1366,736) 1383.55,736 1460.05,812.5 C12.1@1468,812.5
PA_BUS: C13.1 C22.1 C31.1 J3.A4 J3.A9 J3.B4 J3.B9 U1.10 | length 641.5
  Top Layer w10: U1.10@1328.96,632.01 1376.15,632.01 ; J3.B9@1678.07,641.73 1676.1,639.76 J3.A4@1628.46,639.76 1600.24,639.76 1586.02,625.55 1566.44,625.55 1549,642.98 1549,735.5 1551.69,738.19 J3.A9@1628.46,738.19 1676.1,738.19 J3.B4@1678.07,736.22
  Signal Layer 2 w10: v1(1387.01,592.69) 1388.01,593.69 v1(1388.01,621.69) 1401.08,621.69 1507,727.61 1509.61,725 v1(1512,725) 1512,730 1511,731 v1(1511,754)
PA_CC1: C41.1 J3.A5 R6.2 U1.7 | length 571.9
  Top Layer w10: U1.7@1302.38,591.16 1302.38,562.32 1313,551.71 v2(1313,549) ; v2(1584,650) 1584,652 1591,659 1628.02,659 J3.A5@1628.46,659.45
  Signal Layer 2 w10: v2(1313,549) 1313,541 1336,518 1414,518 1546,650 v2(1584,650)
  Bottom Layer w10: v2(1313,549) 1325,537 R6.2@1325,455.62 ; C41.1@1560.62,635 C41.1@1561.12,635 1577,635 1584,642 v2(1584,650)
PA_CC2: C42.1 J3.B5 U1.8 | length 801.7
  Top Layer w10: U1.8@1322.07,591.16 1322.07,569.51 1322.49,569.51 v2(1335,557)
  Signal Layer 2 w10: v2(1335,557) 1348.5,543.5 1407.5,543.5 1534,670 1616,670 1632.55,653.45 1632.55,586 1665,553.55 1714.55,553.55 1739,578 1739,687.1 J3.B5@1705.63,720.47
  Bottom Layer w10: J3.B5@1705.63,720.47 C42.1@1751.38,720.47
PA_DM: C39.1 J3.A7 J3.B7 U1.5 | length 740.9
  Top Layer w10: v2@1263.01,547.58 U1.5@1263.01,594.61 ; v2(1587,714) 1587,712.06 1600.24,698.82 J3.A7@1628.46,698.82
  Signal Layer 2 w10: v2(1265,544) 1265,550.28 1283.86,569.14 1304,569.14 1356.86,622 1356.86,639.69 1357.09,639.69 1506.4,789 1554,789 1609.06,733.94 ; v2(1587,714) 1589.12,714 1609.06,733.94 ; J3.B7@1678.07,673.23 1669.77,673.23 1609.06,733.94
  Bottom Layer w10: C39.1@1565,743 1587,721 v2(1587,714)
PA_DP: C40.1 J3.A6 J3.B6 U1.4 | length 815.3
  Top Layer w10: v2@1243.33,552.01 U1.4@1243.33,594.61 ; v2(1583,690) 1583,689 1592.87,679.13 J3.A6@1628.46,679.13
  Signal Layer 2 w10: v2(1242,549) 1242,552.74 1282.95,593.69 1294.07,593.69 1338.86,638.48 1338.86,650 1495.86,807 1567,807 1669.28,704.72 J3.B6@1678.07,704.72
  Bottom Layer w10: C40.1@1560.62,685 C40.1@1562.62,687 ; C40.1@1561.12,685 1644,685 1663.72,704.72 J3.B6@1678.07,704.72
